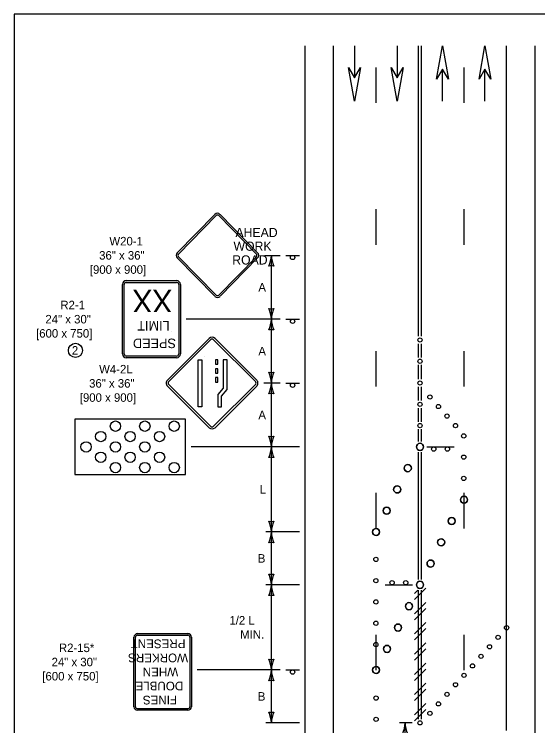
# Model space of a CAD drawing. Extents: x 49991.4 to 50021, y 49987.6 to 50011.4.
# Drawn here: x 50000.34 to 50004.03, y 50006.25 to 50011.26 of the extents above; entities that cross this region are included whole.
import ezdxf

# ---------------------------------------------------------------- set-up
doc = ezdxf.new("R2010")
doc.units = 0
for name, color, linetype in [('Level 1', 7, 'Continuous'), ('Level 2', 7, 'Continuous'), ('Level 3', 7, 'Continuous')]:
    doc.layers.add(name, color=color, linetype=linetype)

msp = doc.modelspace()

# ---------------------------------------------------------------- linework, layer by layer
at = {"layer": 'Level 1'}
for p, q in [((50002.386, 50000.2848), (50002.386, 50011.0404)), ((50002.586, 50000.2848), (50002.586, 50011.0404)), ((50002.7338, 50011.0404), (50002.7338, 50010.8145)), ((50002.734, 50011.0404), (50002.734, 50010.8145)), ((50003.0343, 50011.0404), (50003.0343, 50010.8145)), ((50003.0345, 50011.0404), (50003.0345, 50010.8145)), ((50003.186, 50008.9927), (50003.186, 50011.0404)), ((50003.206, 50008.9927), (50003.206, 50011.0404)), ((50003.806, 50006.2147), (50003.806, 50011.0404)), ((50004.006, 50011.0404), (50004.006, 50000.2848)), ((50002.8861, 50010.6382), (50002.8861, 50010.8882)), ((50003.3549, 50010.6503), (50003.3549, 50010.8762)), ((50003.3553, 50010.6503), (50003.3553, 50010.8762)), ((50003.5061, 50010.6382), (50003.5061, 50010.8882)), ((50003.6535, 50010.6503), (50003.6535, 50010.8762)), ((50003.6539, 50010.6503), (50003.6539, 50010.8762)), ((50002.8861, 50009.6382), (50002.8861, 50009.8882)), ((50003.5061, 50009.6382), (50003.5061, 50009.8882)), ((50001.4847, 50009.5812), (50001.7498, 50009.8519)), ((50001.4935, 50009.5725), (50001.7587, 50009.8432)), ((50001.7773, 50009.8432), (50002.0425, 50009.5725)), ((50001.7861, 50009.8519), (50002.0513, 50009.5812)), ((50001.7498, 50009.2743), (50001.4847, 50009.545)), ((50001.7587, 50009.283), (50001.4935, 50009.5537)), ((50002.0425, 50009.5537), (50001.7773, 50009.283)), ((50002.0513, 50009.545), (50001.7861, 50009.2743)), ((50002.25, 50009.5632), (50002.346, 50009.5632)), ((50001.1254, 50009.3851), (50001.4799, 50009.3851)), ((50001.0982, 50008.8684), (50001.0982, 50009.3579)), ((50001.1106, 50008.8684), (50001.1106, 50009.3579)), ((50001.1254, 50009.3727), (50001.4799, 50009.3727)), ((50001.4947, 50009.3579), (50001.4947, 50008.8684)), ((50001.5071, 50009.3579), (50001.5071, 50008.8684)), ((50002.25, 50009.1132), (50002.346, 50009.1132)), ((50001.4429, 50009.0297), (50001.4429, 50009.0297)), ((50001.7092, 50008.9782), (50001.4151, 50008.6842)), ((50001.4251, 50008.6742), (50001.7191, 50008.9683)), ((50001.7413, 50008.9683), (50002.0353, 50008.6742)), ((50002.0452, 50008.6842), (50001.7512, 50008.9782)), ((50003.1861, 50008.8427), (50003.1861, 50008.9403)), ((50003.2061, 50008.8427), (50003.2061, 50008.9403)), ((50002.8861, 50008.6382), (50002.8861, 50008.8882)), ((50003.5061, 50008.6382), (50003.5061, 50008.8882)), ((50001.4799, 50008.8536), (50001.1254, 50008.8536)), ((50001.4799, 50008.8412), (50001.1254, 50008.8412)), ((50001.6315, 50008.8273), (50001.659, 50008.8273)), ((50001.6315, 50008.4957), (50001.6315, 50008.8273)), ((50001.659, 50008.8273), (50001.659, 50008.4957)), ((50001.7697, 50008.8273), (50001.7551, 50008.8273)), ((50001.7551, 50008.8273), (50001.7551, 50008.7958)), ((50001.7551, 50008.7958), (50001.7697, 50008.7958)), ((50001.7697, 50008.7958), (50001.7697, 50008.8273)), ((50001.8367, 50008.8273), (50001.8092, 50008.8273)), ((50001.8092, 50008.8273), (50001.8092, 50008.6271)), ((50001.8367, 50008.6169), (50001.8367, 50008.8273)), ((50003.1861, 50008.6894), (50003.1861, 50008.7903)), ((50003.2061, 50008.6894), (50003.2061, 50008.7903)), ((50001.7701, 50008.7643), (50001.7555, 50008.7643)), ((50001.7555, 50008.7643), (50001.7555, 50008.7329)), ((50001.7555, 50008.7329), (50001.7701, 50008.7329)), ((50001.7701, 50008.7329), (50001.7701, 50008.7643)), ((50001.7701, 50008.7013), (50001.7555, 50008.7013)), ((50001.7555, 50008.7013), (50001.7555, 50008.6699)), ((50001.7701, 50008.6699), (50001.7701, 50008.7013)), ((50001.4151, 50008.6422), (50001.7092, 50008.3481)), ((50001.7191, 50008.358), (50001.4251, 50008.6521)), ((50002.0353, 50008.6521), (50001.7413, 50008.358)), ((50001.7512, 50008.3481), (50002.0452, 50008.6422)), ((50001.7555, 50008.6699), (50001.7701, 50008.6699)), ((50002.25, 50008.6632), (50002.346, 50008.6632)), ((50003.1861, 50008.5394), (50003.1861, 50008.637)), ((50003.2061, 50008.5394), (50003.2061, 50008.637)), ((50001.8092, 50008.6271), (50001.7698, 50008.5814)), ((50001.7973, 50008.5712), (50001.8367, 50008.6169)), ((50001.7698, 50008.5814), (50001.7698, 50008.4957)), ((50001.7973, 50008.4957), (50001.7973, 50008.5712)), ((50001.659, 50008.4957), (50001.6315, 50008.4957)), ((50001.7698, 50008.4957), (50001.7973, 50008.4957)), ((50003.1861, 50008.3894), (50003.1861, 50008.487)), ((50003.2061, 50008.3894), (50003.2061, 50008.487)), ((50001.7191, 50008.358), (50001.7191, 50008.358)), ((50003.1861, 50008.2513), (50003.1861, 50008.337)), ((50003.2061, 50008.2513), (50003.2061, 50008.337)), ((50003.2449, 50008.2132), (50003.3409, 50008.2132)), ((50003.3409, 50008.2132), (50003.4369, 50008.2132)), ((50003.186, 50007.2783), (50003.186, 50008.1751)), ((50003.206, 50007.2783), (50003.206, 50008.1751)), ((50002.8861, 50007.6382), (50002.8861, 50007.8882)), ((50003.5061, 50007.6382), (50003.5061, 50007.8882)), ((50002.9511, 50007.2406), (50003.0471, 50007.2406)), ((50003.0471, 50007.2406), (50003.1431, 50007.2406)), ((50003.156, 50007.1368), (50003.236, 50007.2168)), ((50003.156, 50007.1792), (50003.1797, 50007.2029)), ((50003.186, 50006.294), (50003.186, 50007.2029)), ((50003.206, 50006.294), (50003.206, 50007.2029)), ((50003.156, 50007.0368), (50003.236, 50007.1168)), ((50003.156, 50006.9943), (50003.236, 50007.0743)), ((50003.156, 50006.8943), (50003.236, 50006.9743)), ((50003.156, 50006.8519), (50003.236, 50006.9319)), ((50001.2049, 50006.8966), (50001.5593, 50006.8966)), ((50001.2049, 50006.886), (50001.5593, 50006.886)), ((50002.8861, 50006.6382), (50002.8861, 50006.8882)), ((50003.5061, 50006.6382), (50003.5061, 50006.8882)), ((50001.1796, 50006.3818), (50001.1796, 50006.8712)), ((50001.1901, 50006.3818), (50001.1901, 50006.8712)), ((50001.5741, 50006.8712), (50001.5741, 50006.3818)), ((50001.5846, 50006.8712), (50001.5846, 50006.3818)), ((50003.156, 50006.7519), (50003.236, 50006.8319)), ((50003.156, 50006.7095), (50003.236, 50006.7895)), ((50003.156, 50006.6095), (50003.236, 50006.6895)), ((50002.25, 50006.6406), (50002.346, 50006.6406)), ((50003.156, 50006.567), (50003.236, 50006.647)), ((50003.156, 50006.467), (50003.236, 50006.547)), ((50003.156, 50006.4246), (50003.236, 50006.5046)), ((50003.156, 50006.3246), (50003.236, 50006.4046)), ((50001.5593, 50006.367), (50001.2049, 50006.367)), ((50001.5593, 50006.3565), (50001.2049, 50006.3565)), ((50001.3821, 50006.3565), (50001.3821, 50006.3565)), ((50003.156, 50006.2822), (50003.236, 50006.3622))]:
    msp.add_line(p, q, dxfattribs=at)
for points in [[(50008.6146, 50011.2628), (50000.3356, 50011.2628), (50000.3356, 50000.0624), (50008.6146, 50000.0624)], [(50003.3133, 50010.8039), (50003.3549, 50011.0404), (50003.3969, 50010.8039), (50003.3549, 50010.8761)], [(50003.6119, 50010.8039), (50003.6535, 50011.0404), (50003.6955, 50010.8039), (50003.6535, 50010.8761)], [(50002.7758, 50010.8868), (50002.734, 50010.6503), (50002.6922, 50010.8868), (50002.734, 50010.8146)], [(50003.0763, 50010.8868), (50003.0345, 50010.6503), (50002.9927, 50010.8868), (50003.0345, 50010.8146)], [(50000.7629, 50008.0182), (50001.5426, 50008.0182), (50001.5426, 50008.4082), (50000.7629, 50008.4082)], [(50000.7629, 50008.0182), (50001.5426, 50008.0182), (50001.5426, 50008.4082), (50000.7629, 50008.4082)]]:
    msp.add_lwpolyline(points, close=True, dxfattribs=at)
msp.add_lwpolyline([(50001.6771, 50008.848), (50001.6774, 50008.8477)], dxfattribs=at)
for centre, radius in [((50002.298, 50009.548), 0.0152), ((50002.298, 50009.098), 0.0152), ((50003.1961, 50008.9665), 0.015), ((50003.1961, 50008.8165), 0.015), ((50002.298, 50008.648), 0.0152), ((50003.1961, 50008.6632), 0.015), ((50003.266, 50008.5645), 0.015), ((50003.1961, 50008.5132), 0.015), ((50003.326, 50008.4975), 0.015), ((50003.3861, 50008.4304), 0.015), ((50001.0491, 50008.3591), 0.0366), ((50001.0491, 50008.3591), 0.0366), ((50001.2562, 50008.3591), 0.0366), ((50001.2562, 50008.3591), 0.0366), ((50001.4633, 50008.3591), 0.0366), ((50001.4633, 50008.3591), 0.0366), ((50003.1961, 50008.3632), 0.015), ((50003.4461, 50008.3633), 0.015), ((50000.9455, 50008.286), 0.0366), ((50000.9455, 50008.286), 0.0366), ((50001.1526, 50008.286), 0.0366), ((50001.1526, 50008.286), 0.0366), ((50001.3598, 50008.286), 0.0366), ((50001.3598, 50008.286), 0.0366), ((50003.5042, 50008.2906), 0.015), ((50000.8419, 50008.2129), 0.0366), ((50000.8419, 50008.2129), 0.0366), ((50001.0491, 50008.2129), 0.0366), ((50001.0491, 50008.2129), 0.0366), ((50001.2562, 50008.2129), 0.0366), ((50001.2562, 50008.2129), 0.0366), ((50003.1961, 50008.2132), 0.025), ((50003.2929, 50008.198), 0.0152), ((50003.3889, 50008.198), 0.0152), ((50000.9455, 50008.1398), 0.0366), ((50000.9455, 50008.1398), 0.0366), ((50001.1526, 50008.1398), 0.0366), ((50001.1526, 50008.1398), 0.0366), ((50001.3598, 50008.1398), 0.0366), ((50001.3598, 50008.1398), 0.0366), ((50003.5042, 50008.1406), 0.015), ((50001.0491, 50008.0667), 0.0366), ((50001.0491, 50008.0667), 0.0366), ((50001.2562, 50008.0667), 0.0366), ((50001.2562, 50008.0667), 0.0366), ((50001.4633, 50008.0667), 0.0366), ((50001.4633, 50008.0667), 0.0366), ((50003.1098, 50008.0632), 0.025), ((50003.5042, 50007.9906), 0.015), ((50003.0352, 50007.9132), 0.025), ((50003.5057, 50007.8406), 0.025), ((50002.9607, 50007.7632), 0.025), ((50003.4193, 50007.6906), 0.025), ((50002.8861, 50007.6132), 0.025), ((50003.3448, 50007.5406), 0.025), ((50002.8846, 50007.42), 0.015), ((50003.2702, 50007.3906), 0.025), ((50002.8846, 50007.27), 0.015), ((50002.9991, 50007.2558), 0.0152), ((50003.0951, 50007.2558), 0.0152), ((50003.1957, 50007.2406), 0.025), ((50002.8846, 50007.12), 0.015), ((50003.1183, 50007.09), 0.025), ((50002.8846, 50006.97), 0.015), ((50003.0409, 50006.9394), 0.025), ((50003.806, 50006.9379), 0.015), ((50003.746, 50006.8708), 0.015), ((50002.8846, 50006.82), 0.015), ((50002.9635, 50006.7888), 0.025), ((50003.6859, 50006.8037), 0.015), ((50003.6259, 50006.7367), 0.015), ((50003.5659, 50006.6696), 0.015), ((50002.298, 50006.6254), 0.0152), ((50002.8861, 50006.6406), 0.025), ((50003.5061, 50006.6029), 0.015), ((50003.4461, 50006.5358), 0.015), ((50003.3861, 50006.4687), 0.015), ((50002.8861, 50006.4423), 0.015), ((50003.326, 50006.4017), 0.015), ((50003.266, 50006.3346), 0.015), ((50002.8861, 50006.2923), 0.015), ((50003.196, 50006.2678), 0.015)]:
    msp.add_circle(centre, radius, dxfattribs=at)
for centre, radius, start, end in [((50001.1254, 50009.3579), 0.0272, 90, 180), ((50001.4799, 50009.3579), 0.0272, 360, 90), ((50001.1254, 50009.3579), 0.0148, 90, 180), ((50001.4799, 50009.3579), 0.0148, 360, 90), ((50001.7302, 50008.9572), 0.0297, 45.0001, 134.9999), ((50001.7302, 50008.9572), 0.0157, 45.0001, 134.9999), ((50001.1254, 50008.8684), 0.0272, 180, 270), ((50001.1254, 50008.8684), 0.0148, 180, 270), ((50001.4799, 50008.8684), 0.0148, 270, 360), ((50001.4799, 50008.8684), 0.0272, 270, 360), ((50001.4361, 50008.6632), 0.0297, 134.9999, 225.0001), ((50002.0242, 50008.6632), 0.0297, 314.9999, 45.0001), ((50001.4361, 50008.6632), 0.0157, 134.9999, 225.0001), ((50002.0242, 50008.6632), 0.0157, 314.9999, 45.0001), ((50001.7302, 50008.3691), 0.0297, 225.0001, 314.9999), ((50001.7302, 50008.3691), 0.0157, 225.0001, 314.9999), ((50003.1961, 50008.2132), 0.025, 0, 180), ((50003.1961, 50008.2132), 0.025, 180, 0), ((50003.1098, 50008.0632), 0.025, 0, 180), ((50003.1098, 50008.0632), 0.025, 180, 0), ((50003.0352, 50007.9132), 0.025, 0, 180), ((50003.0352, 50007.9132), 0.025, 180, 0), ((50003.5057, 50007.8406), 0.025, 0, 180), ((50003.5057, 50007.8406), 0.025, 180, 0), ((50002.9607, 50007.7632), 0.025, 0, 180), ((50002.9607, 50007.7632), 0.025, 180, 0), ((50003.4193, 50007.6906), 0.025, 0, 180), ((50003.4193, 50007.6906), 0.025, 180, 0), ((50002.8861, 50007.6132), 0.025, 360, 180), ((50002.8861, 50007.6132), 0.025, 180, 0), ((50003.3448, 50007.5406), 0.025, 0, 180), ((50003.3448, 50007.5406), 0.025, 180, 0), ((50003.2702, 50007.3906), 0.025, 0, 180), ((50003.2702, 50007.3906), 0.025, 180, 0), ((50003.1957, 50007.2406), 0.025, 0, 180), ((50003.1957, 50007.2406), 0.025, 180, 0), ((50003.1183, 50007.09), 0.025, 0, 180), ((50003.1183, 50007.09), 0.025, 180, 0), ((50003.0409, 50006.9394), 0.025, 0, 180), ((50003.0409, 50006.9394), 0.025, 180, 0), ((50001.2049, 50006.8712), 0.0253, 90, 180), ((50001.2049, 50006.8712), 0.0148, 90, 180), ((50001.5593, 50006.8712), 0.0253, 360, 90), ((50001.5593, 50006.8712), 0.0148, 360, 90), ((50002.9635, 50006.7888), 0.025, 0, 180), ((50002.9635, 50006.7888), 0.025, 180, 0), ((50002.8861, 50006.6406), 0.025, 360, 180), ((50002.8861, 50006.6406), 0.025, 180, 0), ((50001.2049, 50006.3818), 0.0253, 180, 270), ((50001.2049, 50006.3818), 0.0148, 180, 270), ((50001.5593, 50006.3818), 0.0148, 270, 360), ((50001.5593, 50006.3818), 0.0253, 270, 360)]:
    msp.add_arc(centre, radius, start, end, dxfattribs=at)
for centre, major_axis, ratio, start_param, end_param in [((50001.768, 50009.8338), (0, 0.0258), 0.98963, 5.497795, 7.068583), ((50001.768, 50009.8338), (0, 0.0134), 0.98, 5.497795, 7.068583), ((50001.5028, 50009.5631), (0, -0.0258), 0.98963, 3.926991, 5.497787), ((50001.5028, 50009.5631), (0, -0.0134), 0.98, 3.926991, 5.497787), ((50002.0332, 50009.5631), (0, -0.0134), 0.98, 0.785394, 2.356194), ((50002.0332, 50009.5631), (0, -0.0258), 0.98963, 0.785394, 2.356194), ((50001.768, 50009.2925), (0, -0.0258), 0.98963, 5.497787, 7.068583), ((50001.768, 50009.2925), (0, -0.0134), 0.98, 5.497787, 7.068583)]:
    msp.add_ellipse(centre, major_axis=major_axis, ratio=ratio, start_param=start_param, end_param=end_param, dxfattribs=at)
at = {"layer": 'Level 2'}
msp.add_circle((50000.7671, 50008.8932), 0.0501, dxfattribs=at)
at = {"layer": 'Level 3'}
for p, q in [((50002.0987, 50009.5631), (50002.21, 50009.5632)), ((50002.148, 50009.1132), (50002.148, 50009.5632)), ((50002.21, 50009.1132), (50001.5471, 50009.1132)), ((50002.148, 50008.6632), (50002.148, 50009.1132)), ((50002.21, 50008.6632), (50002.0939, 50008.6632)), ((50002.148, 50008.2132), (50002.148, 50008.6632)), ((50002.346, 50008.2132), (50001.5826, 50008.2132)), ((50002.148, 50007.6132), (50002.148, 50008.2132)), ((50002.346, 50007.6132), (50002.108, 50007.6132)), ((50002.148, 50007.2406), (50002.148, 50007.6132)), ((50002.346, 50007.2406), (50002.108, 50007.2406)), ((50002.148, 50006.6406), (50002.148, 50007.2406)), ((50002.21, 50006.6406), (50001.6246, 50006.6406)), ((50002.148, 50006.2679), (50002.148, 50006.6406)), ((50002.346, 50006.2679), (50002.108, 50006.2679)), ((50003.141, 50006.2679), (50003.0506, 50006.2679)), ((50003.0906, 50005.0677), (50003.0906, 50006.2679))]:
    msp.add_line(p, q, dxfattribs=at)
msp.add_lwpolyline([(50001.6246, 50006.6406), (50001.6246, 50006.6406)], dxfattribs=at)
for centre, radius, start, end in [((50001.9153, 50009.5746), 0.233, 337.9228, 357.1727), ((50002.3701, 50009.5723), 0.2223, 182.3605, 202.544), ((50002.148, 50009.4349), 0.0548, 72.1388, 107.8612), ((50001.9259, 50009.104), 0.2223, 2.3605, 22.544), ((50002.148, 50009.2414), 0.0548, 252.1388, 287.8612), ((50002.3807, 50009.1017), 0.233, 157.9228, 177.1727), ((50001.9153, 50009.1247), 0.233, 337.9228, 357.1727), ((50002.3701, 50009.1223), 0.2223, 182.3605, 202.544), ((50002.148, 50008.9849), 0.0548, 72.1388, 107.8612), ((50001.9259, 50008.654), 0.2223, 2.3605, 22.544), ((50002.148, 50008.7914), 0.0548, 252.1388, 287.8612), ((50002.3807, 50008.6517), 0.233, 157.9228, 177.1727), ((50001.9259, 50008.6723), 0.2223, 337.456, 357.6395), ((50002.3807, 50008.6747), 0.233, 182.8273, 202.0772), ((50002.148, 50008.5349), 0.0548, 72.1388, 107.8612), ((50002.148, 50008.3414), 0.0548, 252.1388, 287.8612), ((50001.9153, 50008.2017), 0.233, 2.8273, 22.0772), ((50002.3701, 50008.204), 0.2223, 157.456, 177.6395), ((50001.9259, 50008.2223), 0.2223, 337.456, 357.6395), ((50002.3807, 50008.2247), 0.233, 182.8273, 202.0772), ((50002.148, 50008.0849), 0.0548, 72.1388, 107.8612), ((50002.148, 50007.7414), 0.0548, 252.1388, 287.8612), ((50001.9153, 50007.6017), 0.233, 2.8273, 22.0772), ((50002.3701, 50007.604), 0.2223, 157.456, 177.6395), ((50001.9259, 50007.6223), 0.2223, 337.456, 357.6395), ((50002.3807, 50007.6247), 0.233, 182.8273, 202.0772), ((50002.148, 50007.4849), 0.0548, 72.1388, 107.8612), ((50002.148, 50007.3688), 0.0548, 252.1388, 287.8612), ((50001.9153, 50007.2291), 0.233, 2.8273, 22.0772), ((50002.3701, 50007.2314), 0.2223, 157.456, 177.6395), ((50001.9259, 50007.2497), 0.2223, 337.456, 357.6395), ((50002.3807, 50007.2521), 0.233, 182.8273, 202.0772), ((50002.148, 50007.1123), 0.0548, 72.1388, 107.8612), ((50002.148, 50006.7688), 0.0548, 252.1388, 287.8612), ((50001.9153, 50006.6291), 0.233, 2.8273, 22.0772), ((50002.3701, 50006.6314), 0.2223, 157.456, 177.6395), ((50001.9259, 50006.6497), 0.2223, 337.456, 357.6395), ((50002.3807, 50006.6521), 0.233, 182.8273, 202.0772), ((50002.148, 50006.5123), 0.0548, 72.1388, 107.8612), ((50002.148, 50006.3961), 0.0548, 252.1388, 287.8612), ((50001.9153, 50006.2564), 0.233, 2.8273, 22.0772), ((50002.3701, 50006.2587), 0.2223, 157.456, 177.6395), ((50002.8685, 50006.277), 0.2223, 337.456, 357.6395), ((50003.3233, 50006.2793), 0.233, 182.8273, 202.0772)]:
    msp.add_arc(centre, radius, start, end, dxfattribs=at)

# ---------------------------------------------------------------- texts
at = {"layer": 'Level 1'}
for s, height, rotation, p in [('AHEAD', 0.06453, 360, (50001.895, 50009.6921)), ('WORK', 0.06453, 360, (50001.8812, 50009.5954)), ('ROAD', 0.06453, 360, (50001.8722, 50009.4986)), ('XX', 0.15775, 180, (50001.4498, 50009.3221)), ('LIMIT', 0.06696, 180, (50001.4314, 50009.1001)), ('SPEED', 0.06696, 180, (50001.4758, 50008.9763)), ('PRESENT', 0.06118, 180, (50001.5426, 50006.8554)), ('WORKERS', 0.06118, 180, (50001.5607, 50006.7563)), ('WHEN', 0.06118, 180, (50001.4913, 50006.6571)), ('DOUBLE', 0.06118, 180, (50001.5267, 50006.5579)), ('FINES', 0.06118, 180, (50001.4833, 50006.4588))]:
    msp.add_text(s, height=height, rotation=rotation, dxfattribs=at).set_placement(p)
at = {"layer": 'Level 2'}
for s, p in [('W20-1', (50001.0064, 50009.6331)), ('36" x 36"', (50000.9341, 50009.5331)), ('[900 x 900]', (50000.8686, 50009.4331)), ('R2-1', (50000.6606, 50009.1832)), ('24" x 30"', (50000.5551, 50009.0832)), ('[600 x 750]', (50000.4895, 50008.9832)), ('2', (50000.742, 50008.8632)), ('W4-2L', (50000.9341, 50008.7308)), ('36" x 36"', (50000.8633, 50008.6308)), ('[900 x 900]', (50000.7977, 50008.5308)), ('L', (50002.0656, 50007.8832)), ('B', (50002.0525, 50007.3969)), (' 1/2 L', (50001.8301, 50006.9606)), ('MIN.', (50001.9284, 50006.8606)), ('R2-15*', (50000.6505, 50006.7666)), ('24" x 30"', (50000.599, 50006.6666)), ('[600 x 750]', (50000.5334, 50006.5666)), ('B', (50002.0525, 50006.4242))]:
    msp.add_text(s, height=0.06, dxfattribs=at).set_placement(p)
for p in [(50002.0565, 50009.3082), (50002.0565, 50008.8582), (50002.0565, 50008.4082)]:
    msp.add_text('A', height=0.06, rotation=0, dxfattribs=at).set_placement(p)

doc.saveas('drawing.dxf')
